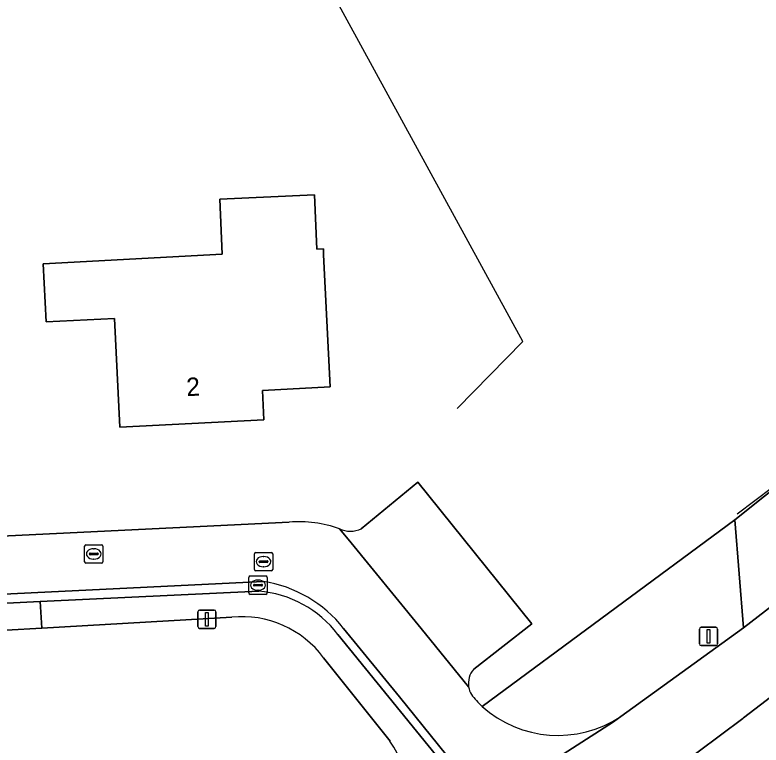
# Model space of a CAD drawing. Extents: x 162156 to 163172, y 378995 to 380779.
# Drawn here: x 162333.04 to 162373.69, y 380227.94 to 380267.71 of the extents above; entities that cross this region are included whole.
import ezdxf

# ---------------------------------------------------------------- set-up
doc = ezdxf.new("R2010")
doc.units = 0
for name, color, linetype in [('IMGEO_Berm_groen', 7, 'Continuous'), ('IMGEO_Erf', 7, 'Continuous'), ('IMGEO_Groenvoorziening', 7, 'Continuous'), ('IMGEO_Hek', 7, 'Continuous'), ('IMGEO_Kolk', 7, 'Continuous'), ('IMGEO_Lichtmast', 7, 'Continuous'), ('IMGEO_Pand', 7, 'Continuous'), ('IMGEO_Pand_nummerreeks', 7, 'Continuous'), ('IMGEO_Parkeervlak_open', 7, 'Continuous'), ('IMGEO_Rijbaan_lokaal_gesloten', 7, 'Continuous'), ('IMGEO_Rijbaan_lokaal_open', 7, 'Continuous'), ('IMGEO_Rioolput', 7, 'Continuous'), ('IMGEO_Voetpad_open', 7, 'Continuous')]:
    doc.layers.add(name, color=color, linetype=linetype)

msp = doc.modelspace()

# ---------------------------------------------------------------- linework, layer by layer
at = {"layer": 'IMGEO_Berm_groen'}
for points in [[(162372.733, 380234.326), (162372.259, 380240.202), (162358.485, 380230.044)], [(162366.037, 380229.487), (162372.733, 380234.326)]]:
    msp.add_lwpolyline(points, dxfattribs=at)
msp.add_arc((162362.623, 380234.673), 6.209, 228.2055, 303.358, dxfattribs=at)
at = {"layer": 'IMGEO_Erf'}
for points in [[(162358.485, 380230.044), (162372.259, 380240.202), (162377.199, 380244.147), (162377.902, 380244.677), (162387.108, 380251.528), (162390.037, 380253.728), (162403.66, 380263.888), (162405.248, 380265.149), (162418.937, 380275.406), (162420.34, 380276.481), (162431.273, 380284.672), (162434.834, 380287.34), (162441.184, 380292.098)], [(162351.908, 380239.719), (162354.985, 380242.257), (162361.203, 380234.535), (162358.029, 380232.064)], [(162316.27, 380238.532), (162347.986, 380240.081)], [(162344.847, 380234.905), (162334.511, 380234.307), (162328.663, 380233.968), (162321.403, 380233.547), (162295.698, 380232.255), (162292.644, 380232.161)], [(162353.471, 380228.147), (162349.856, 380232.689)]]:
    msp.add_lwpolyline(points, dxfattribs=at)
msp.add_lwpolyline([(162349.361, 380257.901), (162349.491, 380254.942), (162349.84, 380254.959), (162349.856, 380254.639), (162350.209, 380247.442), (162346.519, 380247.242), (162346.605, 380245.648), (162338.754, 380245.25), (162338.454, 380251.162), (162334.748, 380250.997), (162334.575, 380254.152), (162344.337, 380254.679), (162344.206, 380257.676)], close=True, dxfattribs=at)
for centre, radius, start, end in [((162348.473, 380233.343), 6.756, 70.5739, 94.1352), ((162351.309, 380241.013), 1.427, 245.634, 294.8483), ((162345.394, 380229.373), 5.559, 36.6187, 95.6517), ((162358.915, 380231.292), 1.175, 138.9233, 188.6444), ((162358.898, 380231.284), 1.158, 188.4153, 211.0113), ((162362.572, 380234.301), 5.902, 217.7501, 226.1653), ((162348.59, 380224.83), 5.901, 19.3293, 34.2034)]:
    msp.add_arc(centre, radius, start, end, dxfattribs=at)
at = {"layer": 'IMGEO_Groenvoorziening'}
msp.add_lwpolyline([(162493.69, 380317.774), (162500, 380321.669), (162508.34, 380326.818), (162512.192, 380329.472), (162511.481, 380331.211), (162505.927, 380327.508), (162484.669, 380313.253), (162476.322, 380307.569), (162468.334, 380301.796), (162450.887, 380288.937), (162395.147, 380246.573), (162372.726, 380229.412), (162372.689, 380229.383), (162370.259, 380227.559), (162363.862, 380222.757), (162350.252, 380212.014), (162347.176, 380208.962)], dxfattribs=at)
msp.add_lwpolyline([(162334.411, 380235.752), (162328.568, 380235.47), (162328.663, 380233.968), (162334.511, 380234.307)], close=True, dxfattribs=at)
at = {"layer": 'IMGEO_Hek'}
for points in [[(162357.137, 380246.264), (162360.716, 380249.917), (162346.027, 380276.771)], [(162377.199, 380244.147), (162372.386, 380240.52)]]:
    msp.add_lwpolyline(points, dxfattribs=at)
at = {"layer": 'IMGEO_Kolk'}
for p, q in [((162345.854, 380237.145), (162346.706, 380237.145)), ((162345.779, 380236.219), (162345.779, 380237.071)), ((162346.267, 380236.925), (162346.292, 380236.925)), ((162346.78, 380237.071), (162346.78, 380236.219)), ((162346.038, 380236.639), (162346.038, 380236.651)), ((162346.476, 380236.602), (162346.078, 380236.602)), ((162346.081, 380236.688), (162346.479, 380236.688)), ((162346.29, 380236.365), (162346.265, 380236.365)), ((162346.522, 380236.651), (162346.522, 380236.639)), ((162346.706, 380236.145), (162345.854, 380236.145))]:
    msp.add_line(p, q, dxfattribs=at)
for points in [[(162345.854, 380237.145), (162346.706, 380237.145)], [(162345.779, 380236.219), (162345.779, 380237.071)], [(162346.78, 380237.071), (162346.78, 380236.219)], [(162346.706, 380236.145), (162345.854, 380236.145)]]:
    msp.add_lwpolyline(points, dxfattribs=at)
for centre, radius, start, end in [((162345.856, 380237.069), 0.0765, 91.552, 178.448), ((162345.856, 380237.069), 0.0765, 91.552, 178.448), ((162346.704, 380237.069), 0.0765, 1.552, 88.448), ((162346.704, 380237.069), 0.0765, 1.552, 88.448), ((162346.078, 380236.648), 0.0403, 85.8775, 175.7526), ((162346.075, 380236.638), 0.0366, 178.938, 274.7102), ((162346.479, 380236.645), 0.043, 264.8664, 352.4533), ((162346.483, 380236.65), 0.0386, 1.7309, 96.639), ((162345.856, 380236.221), 0.0765, 181.552, 268.448), ((162345.856, 380236.221), 0.0765, 181.552, 268.448), ((162346.704, 380236.221), 0.0765, 271.552, 358.448), ((162346.704, 380236.221), 0.0765, 271.552, 358.448)]:
    msp.add_arc(centre, radius, start, end, dxfattribs=at)
for centre, major_axis, ratio, start_param, end_param in [((162346.266, 380236.645), (-0.387, 0.002), 0.722429, 4.712389, 7.853982), ((162346.291, 380236.645), (-0.39, 0.002), 0.717154, 1.570796, 4.712389)]:
    msp.add_ellipse(centre, major_axis=major_axis, ratio=ratio, start_param=start_param, end_param=end_param, dxfattribs=at)
at = {"layer": 'IMGEO_Lichtmast'}
for p, q in [((162343.002, 380234.388), (162343.002, 380235.188)), ((162343.002, 380235.188), (162343.002, 380234.388)), ((162343.102, 380235.288), (162343.892, 380235.288)), ((162343.892, 380235.288), (162343.102, 380235.288)), ((162343.992, 380235.188), (162343.992, 380234.388)), ((162343.992, 380234.388), (162343.992, 380235.188)), ((162370.428, 380234.357), (162371.218, 380234.357)), ((162371.218, 380234.357), (162370.428, 380234.357)), ((162343.892, 380234.288), (162343.102, 380234.288)), ((162343.102, 380234.288), (162343.892, 380234.288)), ((162370.328, 380233.457), (162370.328, 380234.257)), ((162370.328, 380234.257), (162370.328, 380233.457)), ((162371.318, 380234.257), (162371.318, 380233.457)), ((162371.318, 380233.457), (162371.318, 380234.257)), ((162371.218, 380233.357), (162370.428, 380233.357)), ((162370.428, 380233.357), (162371.218, 380233.357))]:
    msp.add_line(p, q, dxfattribs=at)
for points in [[(162343.422, 380235.163), (162343.572, 380235.163), (162343.572, 380234.413), (162343.422, 380234.413), (162343.422, 380235.163)], [(162370.748, 380234.232), (162370.898, 380234.232), (162370.898, 380233.482), (162370.748, 380233.482), (162370.748, 380234.232)]]:
    msp.add_lwpolyline(points, dxfattribs=at)
for centre, start, end in [((162343.102, 380235.188), 90, 180), ((162343.102, 380235.188), 90, 180), ((162343.892, 380235.188), 0, 90), ((162343.892, 380235.188), 360, 90), ((162343.102, 380234.388), 180, 270), ((162343.102, 380234.388), 180, 270), ((162343.892, 380234.388), 270, 0), ((162343.892, 380234.388), 270, 0), ((162370.428, 380234.257), 90, 180), ((162370.428, 380234.257), 90, 180), ((162371.218, 380234.257), 0, 90), ((162371.218, 380234.257), 360, 90), ((162370.428, 380233.457), 180, 270), ((162370.428, 380233.457), 180, 270), ((162371.218, 380233.457), 270, 0), ((162371.218, 380233.457), 270, 0)]:
    msp.add_arc(centre, 0.1, start, end, dxfattribs=at)
at = {"layer": 'IMGEO_Pand'}
msp.add_lwpolyline([(162349.361, 380257.901), (162344.206, 380257.676), (162344.337, 380254.679), (162334.575, 380254.152), (162334.748, 380250.997), (162338.454, 380251.162), (162338.754, 380245.25), (162346.605, 380245.648), (162346.519, 380247.242), (162350.209, 380247.442), (162349.856, 380254.639), (162349.84, 380254.959), (162349.491, 380254.942)], close=True, dxfattribs=at)
at = {"layer": 'IMGEO_Parkeervlak_open'}
for points in [[(162358.029, 380232.064), (162361.203, 380234.535), (162354.985, 380242.257), (162351.908, 380239.719)], [(162350.72, 380239.714), (162351.186, 380239.144), (162355.163, 380234.28), (162357.753, 380231.115)]]:
    msp.add_lwpolyline(points, dxfattribs=at)
for centre, radius, start, end in [((162351.309, 380241.013), 1.427, 245.634, 294.8483), ((162358.915, 380231.292), 1.175, 138.9233, 188.6444)]:
    msp.add_arc(centre, radius, start, end, dxfattribs=at)
at = {"layer": 'IMGEO_Rijbaan_lokaal_gesloten'}
for points in [[(162347.176, 380208.962), (162350.252, 380212.014), (162363.862, 380222.757), (162370.259, 380227.559), (162372.689, 380229.383), (162372.726, 380229.412), (162395.147, 380246.573), (162450.887, 380288.937), (162468.334, 380301.796), (162476.322, 380307.569), (162484.669, 380313.253), (162505.927, 380327.508), (162511.481, 380331.211), (162514.906, 380333.495), (162527.032, 380341.73)], [(162381.999, 380241.493), (162372.733, 380234.326), (162366.037, 380229.487), (162365.645, 380229.204), (162358.695, 380224.728), (162358.331, 380224.494), (162353.288, 380221.289), (162343.433, 380213.084), (162340.006, 380210.284), (162324.772, 380198.212)]]:
    msp.add_lwpolyline(points, dxfattribs=at)
at = {"layer": 'IMGEO_Rijbaan_lokaal_open'}
for points in [[(162347.986, 380240.081), (162316.27, 380238.532)], [(162357.753, 380231.115), (162355.163, 380234.28), (162351.186, 380239.144), (162350.72, 380239.714)], [(162346.564, 380236.852), (162295.236, 380234.347), (162292.702, 380234.286)], [(162292.702, 380234.286), (162295.236, 380234.347), (162346.564, 380236.852)], [(162295.241, 380233.863), (162295.669, 380233.884), (162328.568, 380235.47), (162334.411, 380235.752), (162346.317, 380236.325)], [(162350.638, 380233.965), (162358.331, 380224.494), (162358.695, 380224.728), (162353.988, 380230.568), (162350.941, 380234.293)], [(162350.941, 380234.293), (162353.988, 380230.568), (162358.695, 380224.728), (162365.645, 380229.204), (162366.037, 380229.487)]]:
    msp.add_lwpolyline(points, dxfattribs=at)
for centre, radius, start, end in [((162348.473, 380233.343), 6.756, 70.5739, 94.1352), ((162345.481, 380229.977), 6.96, 38.327, 81.0479), ((162345.481, 380229.977), 6.96, 38.327, 81.0479), ((162345.774, 380230.195), 6.154, 37.777, 84.9389), ((162358.898, 380231.284), 1.158, 188.4153, 211.0113), ((162362.572, 380234.301), 5.902, 217.7501, 226.1653), ((162362.623, 380234.673), 6.209, 228.2055, 303.358)]:
    msp.add_arc(centre, radius, start, end, dxfattribs=at)
at = {"layer": 'IMGEO_Rioolput'}
for p, q in [((162336.833, 380237.922), (162336.833, 380238.774)), ((162336.908, 380238.848), (162337.76, 380238.848)), ((162337.834, 380238.774), (162337.834, 380237.922)), ((162337.135, 380238.391), (162337.533, 380238.391)), ((162337.321, 380238.628), (162337.346, 380238.628)), ((162346.156, 380238.426), (162347.008, 380238.426)), ((162337.092, 380238.342), (162337.092, 380238.354)), ((162337.53, 380238.305), (162337.132, 380238.305)), ((162337.344, 380238.068), (162337.319, 380238.068)), ((162337.576, 380238.354), (162337.576, 380238.342)), ((162346.081, 380237.5), (162346.081, 380238.352)), ((162346.383, 380237.969), (162346.781, 380237.969)), ((162346.569, 380238.206), (162346.594, 380238.206)), ((162347.082, 380238.352), (162347.082, 380237.5)), ((162337.76, 380237.848), (162336.908, 380237.848)), ((162346.34, 380237.92), (162346.34, 380237.932)), ((162346.778, 380237.883), (162346.38, 380237.883)), ((162346.592, 380237.646), (162346.567, 380237.646)), ((162346.824, 380237.932), (162346.824, 380237.92)), ((162347.008, 380237.426), (162346.156, 380237.426))]:
    msp.add_line(p, q, dxfattribs=at)
for points in [[(162336.833, 380237.922), (162336.833, 380238.774)], [(162336.908, 380238.848), (162337.76, 380238.848)], [(162337.834, 380238.774), (162337.834, 380237.922)], [(162346.156, 380238.426), (162347.008, 380238.426)], [(162346.081, 380237.5), (162346.081, 380238.352)], [(162347.082, 380238.352), (162347.082, 380237.5)], [(162337.76, 380237.848), (162336.908, 380237.848)], [(162347.008, 380237.426), (162346.156, 380237.426)]]:
    msp.add_lwpolyline(points, dxfattribs=at)
for centre, radius, start, end in [((162336.91, 380238.772), 0.0765, 91.552, 178.448), ((162336.91, 380238.772), 0.0765, 91.552, 178.448), ((162337.758, 380238.772), 0.0765, 1.552, 88.448), ((162337.758, 380238.772), 0.0765, 1.552, 88.448), ((162337.132, 380238.351), 0.0403, 85.8775, 175.7526), ((162337.537, 380238.353), 0.0386, 1.7309, 96.639), ((162346.158, 380238.35), 0.0765, 91.552, 178.448), ((162346.158, 380238.35), 0.0765, 91.552, 178.448), ((162347.006, 380238.35), 0.0765, 1.552, 88.448), ((162347.006, 380238.35), 0.0765, 1.552, 88.448), ((162337.129, 380238.341), 0.0366, 178.938, 274.7102), ((162337.533, 380238.348), 0.043, 264.8664, 352.4533), ((162346.38, 380237.929), 0.0403, 85.8775, 175.7526), ((162346.785, 380237.931), 0.0386, 1.7309, 96.639), ((162336.91, 380237.924), 0.0765, 181.552, 268.448), ((162336.91, 380237.924), 0.0765, 181.552, 268.448), ((162337.758, 380237.924), 0.0765, 271.552, 358.448), ((162337.758, 380237.924), 0.0765, 271.552, 358.448), ((162346.377, 380237.919), 0.0366, 178.938, 274.7102), ((162346.781, 380237.926), 0.043, 264.8664, 352.4533), ((162346.158, 380237.502), 0.0765, 181.552, 268.448), ((162346.158, 380237.502), 0.0765, 181.552, 268.448), ((162347.006, 380237.502), 0.0765, 271.552, 358.448), ((162347.006, 380237.502), 0.0765, 271.552, 358.448)]:
    msp.add_arc(centre, radius, start, end, dxfattribs=at)
for centre, major_axis, ratio, start_param, end_param in [((162337.32, 380238.348), (-0.387, 0.002), 0.722429, 4.712389, 7.853982), ((162337.345, 380238.348), (-0.39, 0.002), 0.717154, 1.570796, 4.712389), ((162346.568, 380237.926), (-0.387, 0.002), 0.722429, 4.712389, 7.853982), ((162346.593, 380237.926), (-0.39, 0.002), 0.717154, 1.570796, 4.712389)]:
    msp.add_ellipse(centre, major_axis=major_axis, ratio=ratio, start_param=start_param, end_param=end_param, dxfattribs=at)
at = {"layer": 'IMGEO_Voetpad_open'}
msp.add_lwpolyline([(162381.999, 380241.493), (162377.199, 380244.147), (162372.259, 380240.202), (162372.733, 380234.326)], close=True, dxfattribs=at)
for points in [[(162346.317, 380236.325), (162334.411, 380235.752)], [(162334.411, 380235.752), (162334.511, 380234.307), (162344.847, 380234.905)], [(162353.288, 380221.289), (162358.331, 380224.494), (162350.638, 380233.965)], [(162349.856, 380232.689), (162353.471, 380228.147)]]:
    msp.add_lwpolyline(points, dxfattribs=at)
for centre, radius, start, end in [((162345.774, 380230.195), 6.154, 37.777, 84.9389), ((162345.394, 380229.373), 5.559, 36.6187, 95.6517), ((162348.59, 380224.83), 5.901, 19.3293, 34.2034)]:
    msp.add_arc(centre, radius, start, end, dxfattribs=at)

# ---------------------------------------------------------------- texts
at = {"layer": 'IMGEO_Pand_nummerreeks'}
msp.add_text('2', height=1, rotation=2.9049, dxfattribs=at).set_placement((162342.399, 380246.937))

doc.saveas('drawing.dxf')
